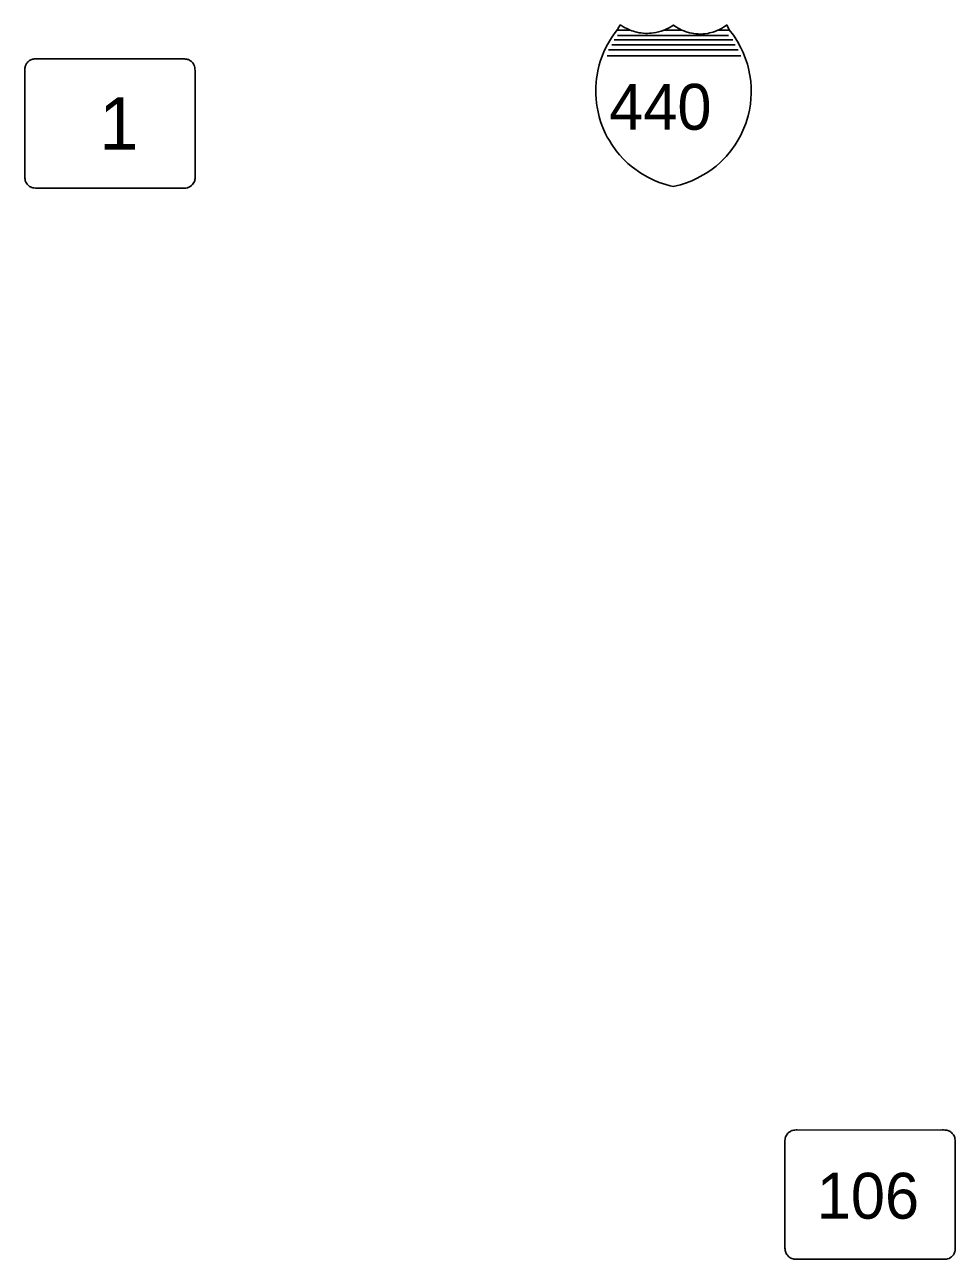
# Model space of a CAD drawing. Extents: x 1612280 to 1883141, y 560852 to 780851.
# Drawn here: x 1722705 to 1730202, y 646323 to 656274 of the extents above; entities that cross this region are included whole.
import ezdxf

# ---------------------------------------------------------------- set-up
doc = ezdxf.new("R2010")
doc.units = 0
doc.layers.add('DESIGN - ROW - Slope Lines', color=7, linetype='Continuous')
doc.layers.add('SURVEY - DRAINAGE - Bridge Hydraulic Data with Text', color=7, linetype='Continuous')

msp = doc.modelspace()

# ---------------------------------------------------------------- linework, layer by layer
at = {"layer": 'DESIGN - ROW - Slope Lines'}
for p, q in [((1722704.8, 655897.3), (1722704.9, 655065.5)), ((1722704.8, 655897.3), (1722704.9, 655065.5)), ((1728829.4, 647264.4), (1728829.4, 646432.6)), ((1728829.4, 647264.4), (1728829.4, 646432.6))]:
    msp.add_line(p, q, dxfattribs=at)
for points in [[(1724077.7, 655886.9), (1724077.6, 655894.7), (1724077.4, 655902.7), (1724076.4, 655917.3), (1724075.1, 655927.8), (1724073.3, 655938.6), (1724071.2, 655944.6), (1724068.1, 655951.2), (1724063.7, 655958.6), (1724058.3, 655966), (1724053.5, 655971.4), (1724047.7, 655977), (1724042.9, 655980.9), (1724036.5, 655985.3), (1724031.5, 655988.3), (1724023.2, 655992.3), (1724017.1, 655994.4), (1724009.9, 655995.8), (1724000.6, 655997.2), (1723992.5, 655998.1), (1723983.9, 655998.6), (1723971.5, 655998.7), (1723962.1, 655998.1), (1722804.8, 655998.7), (1722795.4, 655998.7), (1722785.1, 655998), (1722776, 655996.9), (1722766.9, 655995.2), (1722762.7, 655993.9), (1722755.4, 655990.9), (1722749, 655987.5), (1722743.7, 655984.3), (1722734.8, 655977.4), (1722728.7, 655971.6), (1722723.6, 655965.7), (1722719.7, 655960.4), (1722713.9, 655950.9), (1722710.6, 655943.5), (1722708.6, 655938.3), (1722707.9, 655934.5), (1722707.4, 655931.2), (1722706.6, 655924), (1722705.5, 655914.7), (1722705, 655906.8), (1722704.9, 655900), (1722704.8, 655882.1)], [(1724077.7, 655886.9), (1724077.6, 655894.7), (1724077.4, 655902.7), (1724076.4, 655917.3), (1724075.1, 655927.8), (1724073.3, 655938.6), (1724071.2, 655944.6), (1724068.1, 655951.2), (1724063.7, 655958.6), (1724058.3, 655966), (1724053.5, 655971.4), (1724047.7, 655977), (1724042.9, 655980.9), (1724036.5, 655985.3), (1724031.5, 655988.3), (1724023.2, 655992.3), (1724017.1, 655994.4), (1724009.9, 655995.8), (1724000.6, 655997.2), (1723992.5, 655998.1), (1723983.9, 655998.6), (1723971.5, 655998.7), (1723962.1, 655998.1), (1722804.8, 655998.7), (1722795.4, 655998.7), (1722785.1, 655998), (1722776, 655996.9), (1722766.9, 655995.2), (1722762.7, 655993.9), (1722755.4, 655990.9), (1722749, 655987.5), (1722743.7, 655984.3), (1722734.8, 655977.4), (1722728.7, 655971.6), (1722723.6, 655965.7), (1722719.7, 655960.4), (1722713.9, 655950.9), (1722710.6, 655943.5), (1722708.6, 655938.3), (1722707.9, 655934.5), (1722707.4, 655931.2), (1722706.6, 655924), (1722705.5, 655914.7), (1722705, 655906.8), (1722704.9, 655900), (1722704.8, 655882.1)], [(1723967.9, 654956.2), (1723988.5, 654956.5), (1724005.5, 654956.8), (1724015.8, 654959.2), (1724028.1, 654964), (1724039.2, 654970.4), (1724048.1, 654977.3), (1724056.2, 654985.3), (1724062.5, 654993.2), (1724068.4, 655003), (1724072.1, 655010.8), (1724074.6, 655017.9), (1724076.2, 655025.4), (1724077, 655033.6), (1724077.3, 655043.6), (1724077.7, 655066.9), (1724077.7, 655886.9)], [(1723967.9, 654956.2), (1723988.5, 654956.5), (1724005.5, 654956.8), (1724015.8, 654959.2), (1724028.1, 654964), (1724039.2, 654970.4), (1724048.1, 654977.3), (1724056.2, 654985.3), (1724062.5, 654993.2), (1724068.4, 655003), (1724072.1, 655010.8), (1724074.6, 655017.9), (1724076.2, 655025.4), (1724077, 655033.6), (1724077.3, 655043.6), (1724077.7, 655066.9), (1724077.7, 655886.9)], [(1722704.9, 655065.5), (1722705, 655056.5), (1722705.5, 655046.4), (1722706.3, 655037), (1722707.4, 655027.7), (1722708.8, 655018.5), (1722711.6, 655010.8), (1722715, 655003.7), (1722719.5, 654996.2), (1722724.9, 654988.9), (1722730.5, 654982.7), (1722737.8, 654976.1), (1722744.8, 654970.9), (1722752.7, 654966.1), (1722761.4, 654962.1), (1722770.2, 654959), (1722777.5, 654958.1), (1722792.5, 654956.9), (1722811.3, 654956.2), (1723967.9, 654956.2)], [(1722704.9, 655065.5), (1722705, 655056.5), (1722705.5, 655046.4), (1722706.3, 655037), (1722707.4, 655027.7), (1722708.8, 655018.5), (1722711.6, 655010.8), (1722715, 655003.7), (1722719.5, 654996.2), (1722724.9, 654988.9), (1722730.5, 654982.7), (1722737.8, 654976.1), (1722744.8, 654970.9), (1722752.7, 654966.1), (1722761.4, 654962.1), (1722770.2, 654959), (1722777.5, 654958.1), (1722792.5, 654956.9), (1722811.3, 654956.2), (1723967.9, 654956.2)], [(1730202.3, 647254), (1730202.1, 647261.8), (1730202, 647269.8), (1730201, 647284.4), (1730199.6, 647294.9), (1730197.8, 647305.7), (1730195.8, 647311.7), (1730192.6, 647318.3), (1730188.2, 647325.7), (1730182.8, 647333.1), (1730178.1, 647338.5), (1730172.2, 647344.1), (1730167.5, 647348), (1730161.1, 647352.4), (1730156.1, 647355.4), (1730147.8, 647359.4), (1730141.6, 647361.6), (1730134.5, 647362.9), (1730125.2, 647364.3), (1730117.1, 647365.2), (1730108.4, 647365.7), (1730096.1, 647365.8), (1730086.6, 647365.2), (1728929.4, 647365.8), (1728920, 647365.8), (1728909.7, 647365.1), (1728900.6, 647364), (1728891.5, 647362.3), (1728887.2, 647361), (1728880, 647358), (1728873.5, 647354.6), (1728868.3, 647351.4), (1728859.4, 647344.5), (1728853.3, 647338.7), (1728848.2, 647332.8), (1728844.2, 647327.5), (1728838.5, 647318), (1728835.1, 647310.6), (1728833.2, 647305.4), (1728832.5, 647301.6), (1728832, 647298.3), (1728831.1, 647291.1), (1728830, 647281.8), (1728829.6, 647273.9), (1728829.5, 647267.1), (1728829.4, 647249.2)], [(1730202.3, 647254), (1730202.1, 647261.8), (1730202, 647269.8), (1730201, 647284.4), (1730199.6, 647294.9), (1730197.8, 647305.7), (1730195.8, 647311.7), (1730192.6, 647318.3), (1730188.2, 647325.7), (1730182.8, 647333.1), (1730178.1, 647338.5), (1730172.2, 647344.1), (1730167.5, 647348), (1730161.1, 647352.4), (1730156.1, 647355.4), (1730147.8, 647359.4), (1730141.6, 647361.6), (1730134.5, 647362.9), (1730125.2, 647364.3), (1730117.1, 647365.2), (1730108.4, 647365.7), (1730096.1, 647365.8), (1730086.6, 647365.2), (1728929.4, 647365.8), (1728920, 647365.8), (1728909.7, 647365.1), (1728900.6, 647364), (1728891.5, 647362.3), (1728887.2, 647361), (1728880, 647358), (1728873.5, 647354.6), (1728868.3, 647351.4), (1728859.4, 647344.5), (1728853.3, 647338.7), (1728848.2, 647332.8), (1728844.2, 647327.5), (1728838.5, 647318), (1728835.1, 647310.6), (1728833.2, 647305.4), (1728832.5, 647301.6), (1728832, 647298.3), (1728831.1, 647291.1), (1728830, 647281.8), (1728829.6, 647273.9), (1728829.5, 647267.1), (1728829.4, 647249.2)], [(1730092.4, 646323.3), (1730113.1, 646323.6), (1730130.1, 646323.9), (1730140.3, 646326.3), (1730152.6, 646331.1), (1730163.7, 646337.5), (1730172.7, 646344.4), (1730180.8, 646352.4), (1730187, 646360.3), (1730193, 646370.1), (1730196.6, 646377.9), (1730199.2, 646385), (1730200.8, 646392.5), (1730201.5, 646400.7), (1730201.9, 646410.7), (1730202.3, 646434), (1730202.3, 647254)], [(1730092.4, 646323.3), (1730113.1, 646323.6), (1730130.1, 646323.9), (1730140.3, 646326.3), (1730152.6, 646331.1), (1730163.7, 646337.5), (1730172.7, 646344.4), (1730180.8, 646352.4), (1730187, 646360.3), (1730193, 646370.1), (1730196.6, 646377.9), (1730199.2, 646385), (1730200.8, 646392.5), (1730201.5, 646400.7), (1730201.9, 646410.7), (1730202.3, 646434), (1730202.3, 647254)], [(1728829.4, 646432.6), (1728829.6, 646423.6), (1728830.1, 646413.5), (1728830.9, 646404.1), (1728832, 646394.8), (1728833.4, 646385.6), (1728836.2, 646377.9), (1728839.6, 646370.8), (1728844.1, 646363.3), (1728849.5, 646356), (1728855.1, 646349.8), (1728862.3, 646343.2), (1728869.3, 646338), (1728877.3, 646333.2), (1728885.9, 646329.2), (1728894.8, 646326.1), (1728902.1, 646325.2), (1728917, 646324), (1728935.8, 646323.3), (1730092.4, 646323.3)], [(1728829.4, 646432.6), (1728829.6, 646423.6), (1728830.1, 646413.5), (1728830.9, 646404.1), (1728832, 646394.8), (1728833.4, 646385.6), (1728836.2, 646377.9), (1728839.6, 646370.8), (1728844.1, 646363.3), (1728849.5, 646356), (1728855.1, 646349.8), (1728862.3, 646343.2), (1728869.3, 646338), (1728877.3, 646333.2), (1728885.9, 646329.2), (1728894.8, 646326.1), (1728902.1, 646325.2), (1728917, 646324), (1728935.8, 646323.3), (1730092.4, 646323.3)]]:
    msp.add_lwpolyline(points, dxfattribs=at)
at = {"layer": 'SURVEY - DRAINAGE - Bridge Hydraulic Data with Text'}
for p, q in [((1727453.1, 656151.6), (1728408.9, 656151.7)), ((1727453.1, 656151.6), (1728408.9, 656151.7)), ((1727476.8, 656228.7), (1727583.4, 656228.7)), ((1727476.8, 656228.7), (1727583.4, 656228.7)), ((1727480.8, 656185.5), (1728374.9, 656185.5)), ((1727480.8, 656185.5), (1728374.9, 656185.5)), ((1727852.6, 656228.7), (1727999.9, 656228.7)), ((1727852.6, 656228.7), (1727999.9, 656228.7)), ((1728285.4, 656228.7), (1728385.2, 656228.7)), ((1728285.4, 656228.7), (1728385.2, 656228.7)), ((1727408.4, 656072.3), (1728453.6, 656072.3)), ((1727408.4, 656072.3), (1728453.6, 656072.3)), ((1727436.1, 656112.6), (1728428.1, 656112.6)), ((1727436.1, 656112.6), (1728428.1, 656112.6)), ((1727396.7, 656021.6), (1728473.9, 656021.6)), ((1727396.7, 656021.6), (1728473.9, 656021.6))]:
    msp.add_line(p, q, dxfattribs=at)
for points in [[(1727503.5, 656273.9), (1727480.8, 656235), (1727461.8, 656210.6), (1727442.3, 656183.3), (1727431.8, 656167.5), (1727416.3, 656142.4), (1727400.5, 656114.6), (1727382.4, 656079.2), (1727371.6, 656055.6), (1727359.8, 656027.3), (1727342, 655976.8), (1727333.9, 655949.5), (1727327.6, 655925.4), (1727322.2, 655901.2), (1727316, 655868.2), (1727312, 655840.9), (1727308.5, 655809.1), (1727306.3, 655776.1), (1727305.5, 655736.8), (1727306.1, 655708.1), (1727307.9, 655677.8), (1727311.7, 655641.2), (1727316.2, 655610.3), (1727323.9, 655570.5), (1727333.4, 655532), (1727344.9, 655493.7), (1727355.2, 655464.7), (1727368.4, 655431.7), (1727385.2, 655394.8), (1727398.7, 655368.4), (1727415.1, 655339.3), (1727434.7, 655307.9), (1727470.5, 655257.8), (1727497.2, 655225.1), (1727528.2, 655191.4), (1727564.3, 655156.5), (1727601.7, 655124.7), (1727669.1, 655076.6), (1727720.7, 655046.4), (1727779.8, 655017.8), (1727815.8, 655003.3), (1727869.1, 654985.5), (1727905.9, 654975.6), (1727928.7, 654969.9)], [(1727503.5, 656273.9), (1727480.8, 656235), (1727461.8, 656210.6), (1727442.3, 656183.3), (1727431.8, 656167.5), (1727416.3, 656142.4), (1727400.5, 656114.6), (1727382.4, 656079.2), (1727371.6, 656055.6), (1727359.8, 656027.3), (1727342, 655976.8), (1727333.9, 655949.5), (1727327.6, 655925.4), (1727322.2, 655901.2), (1727316, 655868.2), (1727312, 655840.9), (1727308.5, 655809.1), (1727306.3, 655776.1), (1727305.5, 655736.8), (1727306.1, 655708.1), (1727307.9, 655677.8), (1727311.7, 655641.2), (1727316.2, 655610.3), (1727323.9, 655570.5), (1727333.4, 655532), (1727344.9, 655493.7), (1727355.2, 655464.7), (1727368.4, 655431.7), (1727385.2, 655394.8), (1727398.7, 655368.4), (1727415.1, 655339.3), (1727434.7, 655307.9), (1727470.5, 655257.8), (1727497.2, 655225.1), (1727528.2, 655191.4), (1727564.3, 655156.5), (1727601.7, 655124.7), (1727669.1, 655076.6), (1727720.7, 655046.4), (1727779.8, 655017.8), (1727815.8, 655003.3), (1727869.1, 654985.5), (1727905.9, 654975.6), (1727928.7, 654969.9)], [(1728361.8, 656272.6), (1728349.4, 656263.3), (1728334.8, 656253.5), (1728319.8, 656244.5), (1728303.9, 656235.9), (1728291.5, 656229.9), (1728269.7, 656220.9), (1728251.8, 656214.7), (1728223, 656207), (1728207.9, 656203.9), (1728183.4, 656200.4), (1728170.7, 656199.3), (1728154.6, 656198.6), (1728134.3, 656198.7), (1728125.8, 656199.1), (1728111.8, 656200.2), (1728094.8, 656202.3), (1728081.8, 656204.5), (1728061, 656209), (1728033.3, 656217.2), (1728015.3, 656223.9), (1728000, 656230.5), (1727975.7, 656242.9), (1727951.6, 656257.7), (1727932.6, 656271.3), (1727917.8, 656261.4), (1727898.2, 656249.8), (1727877.8, 656239.4), (1727862.2, 656232.5), (1727847.8, 656226.8), (1727831.6, 656221.2), (1727812.4, 656215.7), (1727800.3, 656212.8), (1727789.9, 656210.6), (1727770.8, 656207.4), (1727751.3, 656205.3), (1727737.5, 656204.4), (1727723.5, 656204), (1727705.3, 656204.2), (1727688.2, 656205.3), (1727669, 656207.4), (1727656, 656209.5), (1727636.9, 656213.4), (1727621.8, 656217.2), (1727610.2, 656220.6), (1727595.2, 656225.6), (1727583.5, 656230), (1727572.5, 656234.6), (1727555.2, 656242.6), (1727543, 656249), (1727531.8, 656255.3), (1727516.6, 656264.8), (1727503.5, 656273.9)], [(1728361.8, 656272.6), (1728349.4, 656263.3), (1728334.8, 656253.5), (1728319.8, 656244.5), (1728303.9, 656235.9), (1728291.5, 656229.9), (1728269.7, 656220.9), (1728251.8, 656214.7), (1728223, 656207), (1728207.9, 656203.9), (1728183.4, 656200.4), (1728170.7, 656199.3), (1728154.6, 656198.6), (1728134.3, 656198.7), (1728125.8, 656199.1), (1728111.8, 656200.2), (1728094.8, 656202.3), (1728081.8, 656204.5), (1728061, 656209), (1728033.3, 656217.2), (1728015.3, 656223.9), (1728000, 656230.5), (1727975.7, 656242.9), (1727951.6, 656257.7), (1727932.6, 656271.3), (1727917.8, 656261.4), (1727898.2, 656249.8), (1727877.8, 656239.4), (1727862.2, 656232.5), (1727847.8, 656226.8), (1727831.6, 656221.2), (1727812.4, 656215.7), (1727800.3, 656212.8), (1727789.9, 656210.6), (1727770.8, 656207.4), (1727751.3, 656205.3), (1727737.5, 656204.4), (1727723.5, 656204), (1727705.3, 656204.2), (1727688.2, 656205.3), (1727669, 656207.4), (1727656, 656209.5), (1727636.9, 656213.4), (1727621.8, 656217.2), (1727610.2, 656220.6), (1727595.2, 656225.6), (1727583.5, 656230), (1727572.5, 656234.6), (1727555.2, 656242.6), (1727543, 656249), (1727531.8, 656255.3), (1727516.6, 656264.8), (1727503.5, 656273.9)], [(1728361.8, 656272.6), (1728381.6, 656231.8), (1728414.8, 656188.3), (1728446.9, 656139), (1728475.6, 656086.7), (1728492.6, 656050.4), (1728512.9, 655999.5), (1728527.2, 655955), (1728536.5, 655920.2), (1728547.9, 655863.9), (1728554, 655819.4), (1728557.5, 655771.7), (1728558.2, 655719.7), (1728551.4, 655632.8), (1728543.5, 655584.9), (1728533, 655539.4), (1728514.3, 655478.1), (1728499.3, 655438.6), (1728474.1, 655383.7), (1728453.6, 655345.8), (1728429.3, 655306.5), (1728393.7, 655256.7), (1728355.3, 655211.1), (1728308.9, 655164.2), (1728274.9, 655134.4), (1728232, 655101.3), (1728195.3, 655076.5), (1728122.7, 655035.7), (1728080.4, 655016.4), (1728036.4, 654999.4), (1727987.8, 654984), (1727928.7, 654969.9)], [(1728361.8, 656272.6), (1728381.6, 656231.8), (1728414.8, 656188.3), (1728446.9, 656139), (1728475.6, 656086.7), (1728492.6, 656050.4), (1728512.9, 655999.5), (1728527.2, 655955), (1728536.5, 655920.2), (1728547.9, 655863.9), (1728554, 655819.4), (1728557.5, 655771.7), (1728558.2, 655719.7), (1728551.4, 655632.8), (1728543.5, 655584.9), (1728533, 655539.4), (1728514.3, 655478.1), (1728499.3, 655438.6), (1728474.1, 655383.7), (1728453.6, 655345.8), (1728429.3, 655306.5), (1728393.7, 655256.7), (1728355.3, 655211.1), (1728308.9, 655164.2), (1728274.9, 655134.4), (1728232, 655101.3), (1728195.3, 655076.5), (1728122.7, 655035.7), (1728080.4, 655016.4), (1728036.4, 654999.4), (1727987.8, 654984), (1727928.7, 654969.9)]]:
    msp.add_lwpolyline(points, dxfattribs=at)

# ---------------------------------------------------------------- texts
at = {"layer": 'DESIGN - ROW - Slope Lines'}
for s, height, rotation, p in [('1', 422.4, 0.00108, (1723306.2, 655265.4)), ('1', 422.4, 0.00108, (1723306.2, 655265.4)), ('106', 369.61, 0.00107, (1729086, 646650.7)), ('106', 369.61, 0.00107, (1729086, 646650.7))]:
    msp.add_text(s, height=height, rotation=rotation, dxfattribs=at).set_placement(p)
at = {"layer": 'SURVEY - DRAINAGE - Bridge Hydraulic Data with Text'}
msp.add_text('440', height=369.6, rotation=0.00131, dxfattribs=at).set_placement((1727413.6, 655427.2))
msp.add_text('440', height=369.6, rotation=0.00131, dxfattribs=at).set_placement((1727413.6, 655427.2))

doc.saveas('drawing.dxf')
